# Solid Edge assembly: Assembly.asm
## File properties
Author: Vicky Raina
Template: Normal.asm
Last saved by: MYPC
Revision: 10
Application: Solid Edge
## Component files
Casting.par
Brasses.par
Cap.par
Bolt.par
Nut.par
Lock Nut.par
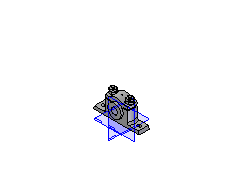
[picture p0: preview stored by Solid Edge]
